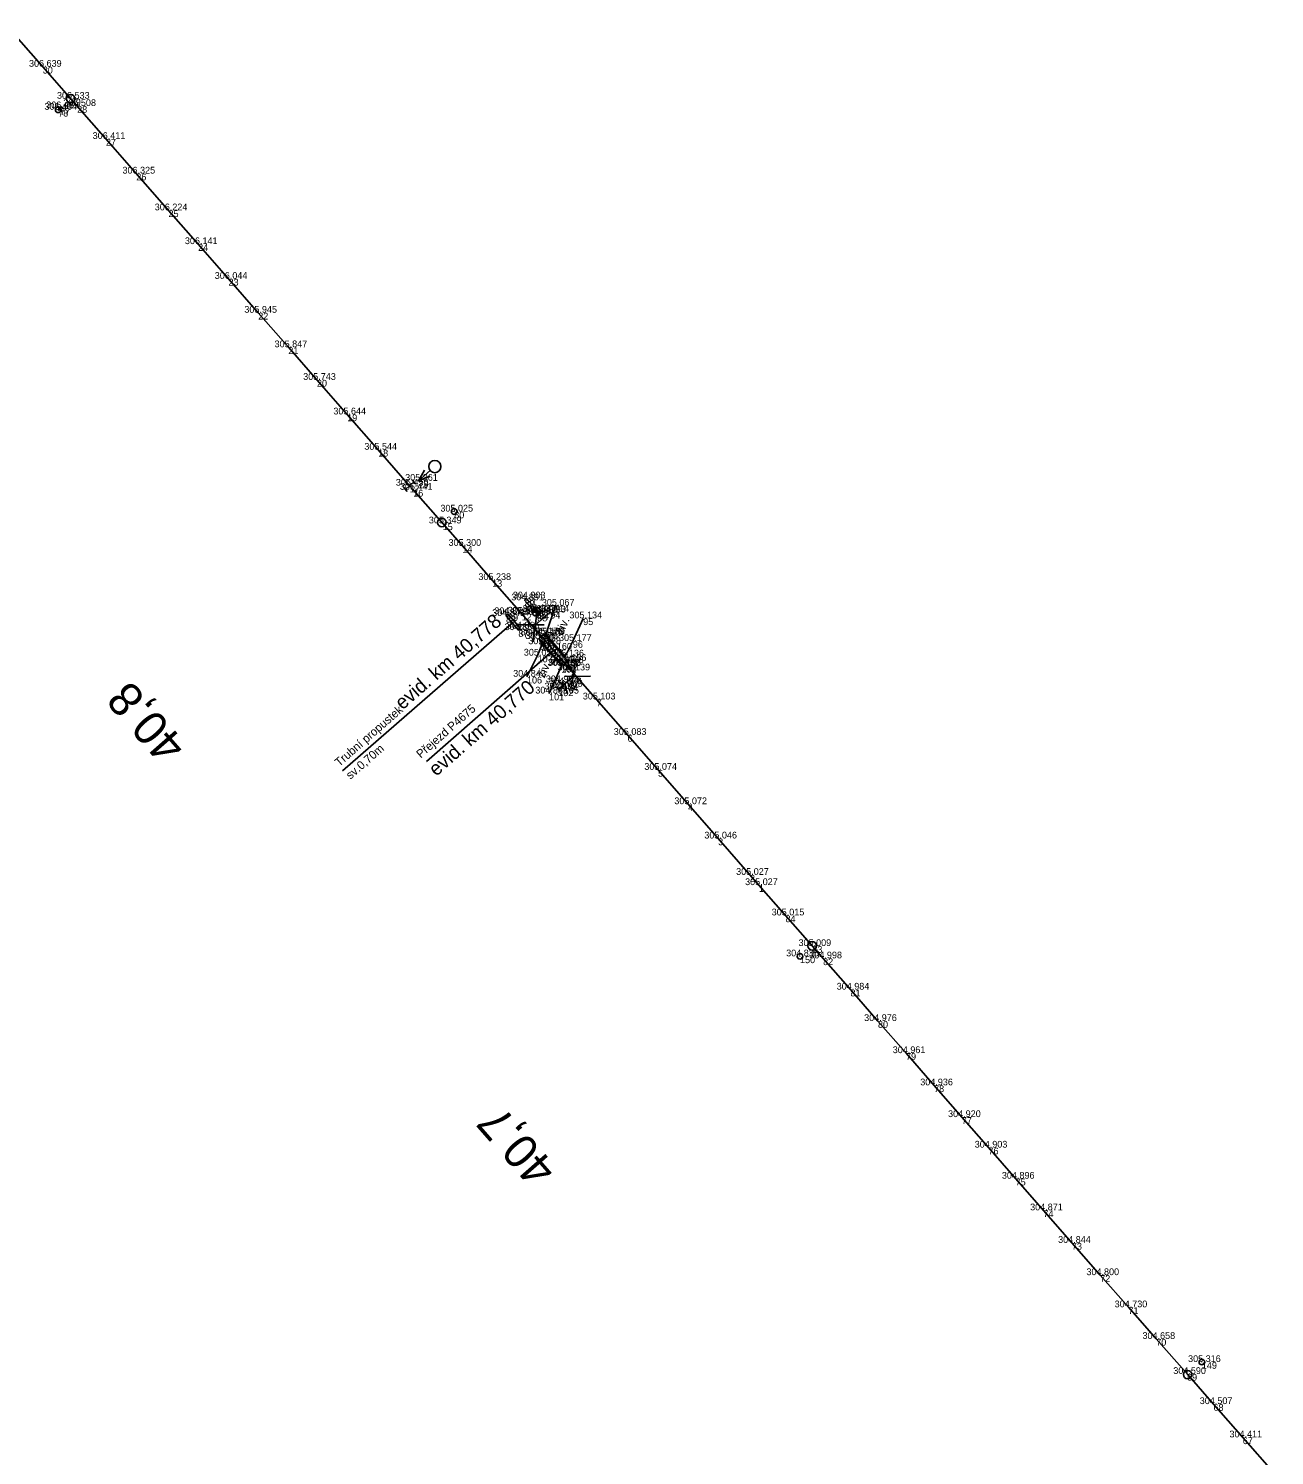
# Model space of a CAD drawing. Extents: x -684938 to -684389, y -1007777 to -1006471.
# Drawn here: x -684817.7 to -684596.3, y -1006797 to -1006543.6 of the extents above; entities that cross this region are included whole.
import ezdxf

# ---------------------------------------------------------------- set-up
doc = ezdxf.new("R2010")
doc.units = 0
for name, color, linetype in [('Vrstva 1', 7, 'Continuous'), ('Vrstva 12', 7, 'Continuous'), ('Vrstva 19', 7, 'Continuous'), ('Vrstva 3', 7, 'Continuous'), ('Vrstva 4', 7, 'Continuous'), ('Vrstva 51', 7, 'Continuous'), ('Vrstva 60', 7, 'Continuous'), ('Vrstva 61', 7, 'Continuous'), ('Vrstva 63', 7, 'Continuous'), ('Vrstva 7', 7, 'Continuous')]:
    doc.layers.add(name, color=color, linetype=linetype)

msp = doc.modelspace()

# ---------------------------------------------------------------- linework, layer by layer
at = {"layer": 'Vrstva 1'}
msp.add_lwpolyline([(-684596.33, -1006800.2), (-684601.97, -1006793.78), (-684607.16, -1006787.87), (-684611.86, -1006782.52), (-684617.33, -1006776.3), (-684622.28, -1006770.68), (-684627.29, -1006764.97), (-684632.32, -1006759.24), (-684637.38, -1006753.46), (-684642.31, -1006747.84), (-684647.14, -1006742.32), (-684651.87, -1006736.9), (-684656.8, -1006731.26), (-684661.79, -1006725.54), (-684666.77, -1006719.84), (-684671.66, -1006714.26), (-684676.52, -1006708.71), (-684678.43, -1006706.52), (-684683.2, -1006701.08), (-684687.93, -1006695.7), (-684689.52, -1006693.88), (-684695.17, -1006687.42), (-684700.5, -1006681.33), (-684705.83, -1006675.23), (-684711.26, -1006669.03), (-684716.76, -1006662.73), (-684721.27, -1006657.57), (-684722.42, -1006656.26), (-684724.49, -1006653.89), (-684726.54, -1006651.55), (-684730.09, -1006647.48), (-684735.31, -1006641.52), (-684740.61, -1006635.45), (-684744.1, -1006631.46), (-684749.34, -1006625.49), (-684749.98, -1006624.76), (-684755.57, -1006618.38), (-684761.07, -1006612.11), (-684766.44, -1006605.97), (-684771.52, -1006600.18), (-684776.88, -1006594.05), (-684782.15, -1006588.03), (-684787.55, -1006581.86), (-684792.81, -1006575.86), (-684798.53, -1006569.33), (-684803.93, -1006563.18), (-684809.04, -1006557.34), (-684810.18, -1006556.04), (-684815.15, -1006550.36), (-684821.1, -1006543.57)], dxfattribs=at)
at = {"layer": 'Vrstva 12'}
msp.add_lwpolyline([(-684723.34, -1006659.67), (-684722.75, -1006660.05), (-684722.58, -1006660.48)], dxfattribs=at)
at = {"layer": 'Vrstva 19'}
msp.add_line((-684761.93, -1006675.41), (-684731.76, -1006649.16), dxfattribs=at)
for points in [[(-684727.31, -1006647.66), (-684729.55, -1006645.12), (-684729.19, -1006644.79), (-684726.95, -1006647.34), (-684727.31, -1006647.66)], [(-684730.26, -1006650.13), (-684732.49, -1006647.58), (-684732.85, -1006647.9), (-684730.66, -1006650.41), (-684730.26, -1006650.13)]]:
    msp.add_lwpolyline(points, dxfattribs=at)
at = {"layer": 'Vrstva 3'}
for p, q in [((-684750.73, -1006625.42), (-684749.22, -1006624.1)), ((-684748.89, -1006624.48), (-684749.55, -1006623.72)), ((-684748.41, -1006623.9), (-684746.33, -1006622.08)), ((-684750.4, -1006625.79), (-684751.06, -1006625.04))]:
    msp.add_line(p, q, dxfattribs=at)
msp.add_lwpolyline([(-684747.31, -1006622.02), (-684748.41, -1006623.9), (-684746.4, -1006623.06)], dxfattribs=at)
msp.add_circle((-684745.51, -1006621.37), 1.08, dxfattribs=at)
at = {"layer": 'Vrstva 4'}
for p, q in [((-684724.98, -1006647.16), (-684727.63, -1006649.47)), ((-684724.66, -1006647.53), (-684725.31, -1006646.78)), ((-684726.1, -1006649.46), (-684730.71, -1006649.5)), ((-684728.08, -1006652.51), (-684727.41, -1006647.95)), ((-684747, -1006673.72), (-684724.43, -1006653.95)), ((-684720.48, -1006655.59), (-684721.14, -1006660.15)), ((-684723.57, -1006660.94), (-684720.92, -1006658.63)), ((-684722.46, -1006658.64), (-684717.85, -1006658.6)), ((-684723.9, -1006660.57), (-684723.24, -1006661.32))]:
    msp.add_line(p, q, dxfattribs=at)
msp.add_lwpolyline([(-684722.88, -1006656.69), (-684727, -1006651.97), (-684726.06, -1006651.16), (-684721.93, -1006655.87), (-684722.88, -1006656.69)], dxfattribs=at)
at = {"layer": 'Vrstva 51'}
for points in [[(-684724.04, -1006646.08), (-684725.76, -1006651.2), (-684722.34, -1006655.1), (-684720.98, -1006652.35), (-684719.14, -1006648.32)], [(-684729.13, -1006658.69), (-684727.24, -1006654.94), (-684726.45, -1006652.91), (-684723.02, -1006656.76), (-684725.2, -1006661.67)]]:
    msp.add_lwpolyline(points, dxfattribs=at)
at = {"layer": 'Vrstva 60'}
for p, q in [((-684815.15, -1006550.36), (-684815.15, -1006550.36)), ((-684810.18, -1006556.04), (-684810.18, -1006556.04)), ((-684812.41, -1006558), (-684812.41, -1006558)), ((-684812.08, -1006557.73), (-684812.08, -1006557.73)), ((-684809.04, -1006557.34), (-684809.04, -1006557.34)), ((-684803.93, -1006563.18), (-684803.93, -1006563.18)), ((-684798.53, -1006569.33), (-684798.53, -1006569.33)), ((-684792.81, -1006575.86), (-684792.81, -1006575.86)), ((-684787.55, -1006581.86), (-684787.55, -1006581.86)), ((-684782.15, -1006588.03), (-684782.15, -1006588.03)), ((-684776.88, -1006594.05), (-684776.88, -1006594.05)), ((-684771.52, -1006600.18), (-684771.52, -1006600.18)), ((-684766.44, -1006605.97), (-684766.44, -1006605.97)), ((-684761.07, -1006612.11), (-684761.07, -1006612.11)), ((-684755.57, -1006618.38), (-684755.57, -1006618.38)), ((-684748.41, -1006623.9), (-684748.41, -1006623.9)), ((-684749.98, -1006624.76), (-684749.98, -1006624.76)), ((-684749.34, -1006625.49), (-684749.34, -1006625.49)), ((-684742.05, -1006629.36), (-684742.05, -1006629.36)), ((-684744.1, -1006631.46), (-684744.1, -1006631.46)), ((-684740.61, -1006635.45), (-684740.61, -1006635.45)), ((-684735.31, -1006641.52), (-684735.31, -1006641.52)), ((-684729.19, -1006644.79), (-684729.19, -1006644.79)), ((-684729.55, -1006645.12), (-684729.55, -1006645.12)), ((-684727.46, -1006647.17), (-684727.46, -1006647.17)), ((-684726.95, -1006647.34), (-684726.95, -1006647.34)), ((-684724.98, -1006647.16), (-684724.98, -1006647.16)), ((-684724.04, -1006646.08), (-684724.04, -1006646.08)), ((-684732.85, -1006647.9), (-684732.85, -1006647.9)), ((-684732.49, -1006647.58), (-684732.49, -1006647.58)), ((-684730.09, -1006647.48), (-684730.09, -1006647.48)), ((-684727.31, -1006647.66), (-684727.31, -1006647.66)), ((-684719.14, -1006648.32), (-684719.14, -1006648.32)), ((-684730.66, -1006650.41), (-684730.66, -1006650.41)), ((-684730.26, -1006650.13), (-684730.26, -1006650.13)), ((-684727, -1006651.97), (-684727, -1006651.97)), ((-684726.54, -1006651.55), (-684726.54, -1006651.55)), ((-684726.06, -1006651.16), (-684726.06, -1006651.16)), ((-684725.76, -1006651.2), (-684725.76, -1006651.2)), ((-684720.98, -1006652.35), (-684720.98, -1006652.35)), ((-684727.24, -1006654.94), (-684727.24, -1006654.94)), ((-684726.45, -1006652.91), (-684726.45, -1006652.91)), ((-684724.49, -1006653.89), (-684724.49, -1006653.89)), ((-684723.02, -1006656.76), (-684723.02, -1006656.76)), ((-684722.88, -1006656.69), (-684722.88, -1006656.69)), ((-684722.42, -1006656.26), (-684722.42, -1006656.26)), ((-684722.34, -1006655.1), (-684722.34, -1006655.1)), ((-684721.93, -1006655.87), (-684721.93, -1006655.87)), ((-684729.13, -1006658.69), (-684729.13, -1006658.69)), ((-684723.34, -1006659.67), (-684723.34, -1006659.67)), ((-684721.27, -1006657.57), (-684721.27, -1006657.57)), ((-684725.2, -1006661.67), (-684725.2, -1006661.67)), ((-684723.57, -1006660.94), (-684723.57, -1006660.94)), ((-684722.75, -1006660.05), (-684722.75, -1006660.05)), ((-684722.58, -1006660.48), (-684722.58, -1006660.48)), ((-684716.76, -1006662.73), (-684716.76, -1006662.73)), ((-684711.26, -1006669.03), (-684711.26, -1006669.03)), ((-684705.83, -1006675.23), (-684705.83, -1006675.23)), ((-684700.5, -1006681.33), (-684700.5, -1006681.33)), ((-684695.17, -1006687.42), (-684695.17, -1006687.42)), ((-684689.52, -1006693.88), (-684689.52, -1006693.88)), ((-684687.93, -1006695.7), (-684687.93, -1006695.7)), ((-684683.2, -1006701.08), (-684683.2, -1006701.08)), ((-684678.43, -1006706.52), (-684678.43, -1006706.52)), ((-684680.62, -1006708.35), (-684680.62, -1006708.35)), ((-684676.52, -1006708.71), (-684676.52, -1006708.71)), ((-684671.66, -1006714.26), (-684671.66, -1006714.26)), ((-684666.77, -1006719.84), (-684666.77, -1006719.84)), ((-684661.79, -1006725.54), (-684661.79, -1006725.54)), ((-684656.8, -1006731.26), (-684656.8, -1006731.26)), ((-684651.87, -1006736.9), (-684651.87, -1006736.9)), ((-684647.14, -1006742.32), (-684647.14, -1006742.32)), ((-684642.31, -1006747.84), (-684642.31, -1006747.84)), ((-684637.38, -1006753.46), (-684637.38, -1006753.46)), ((-684632.32, -1006759.24), (-684632.32, -1006759.24)), ((-684627.29, -1006764.97), (-684627.29, -1006764.97)), ((-684622.28, -1006770.68), (-684622.28, -1006770.68)), ((-684617.33, -1006776.3), (-684617.33, -1006776.3)), ((-684609.23, -1006780.4), (-684609.23, -1006780.4)), ((-684611.86, -1006782.52), (-684611.86, -1006782.52)), ((-684607.16, -1006787.87), (-684607.16, -1006787.87)), ((-684601.97, -1006793.78), (-684601.97, -1006793.78))]:
    msp.add_line(p, q, dxfattribs=at)
at = {"layer": 'Vrstva 63'}
for p, q in [((-684727.46, -1006647.17), (-684728.22, -1006647.12)), ((-684727.44, -1006646.96), (-684728.18, -1006646.91)), ((-684727.42, -1006646.66), (-684727.99, -1006646.62)), ((-684727.51, -1006647.93), (-684727.46, -1006647.17)), ((-684727.41, -1006646.4), (-684727.46, -1006647.17)), ((-684727.46, -1006647.17), (-684726.69, -1006647.22)), ((-684726.91, -1006647.7), (-684727.49, -1006647.66)), ((-684726.73, -1006647.41), (-684727.47, -1006647.36))]:
    msp.add_line(p, q, dxfattribs=at)
msp.add_circle((-684727.46, -1006647.17), 0.764, dxfattribs=at)
for start, end in [(86.1893, 176.0828), (265.7385, 356.0566)]:
    msp.add_arc((-684727.46, -1006647.17), 0.765, start, end, dxfattribs=at)
at = {"layer": 'Vrstva 7'}
for p, q in [((-684812.46, -1006558.05), (-684811.71, -1006557.4)), ((-684812.38, -1006558.03), (-684812.44, -1006557.96)), ((-684811.76, -1006558.1), (-684812.41, -1006557.35)), ((-684742.02, -1006629.4), (-684742.09, -1006629.32)), ((-684680.59, -1006708.39), (-684680.65, -1006708.32)), ((-684609.2, -1006780.44), (-684609.26, -1006780.36))]:
    msp.add_line(p, q, dxfattribs=at)
for centre, radius in [((-684810.18, -1006556.04), 0.75), ((-684812.41, -1006558), 0.5), ((-684742.05, -1006629.36), 0.5), ((-684744.26, -1006631.29), 0.75), ((-684680.62, -1006708.35), 0.5), ((-684678.47, -1006706.48), 0.75), ((-684609.23, -1006780.4), 0.5), ((-684611.76, -1006782.63), 0.75)]:
    msp.add_circle(centre, radius, dxfattribs=at)

# ---------------------------------------------------------------- texts
at = {"layer": 'Vrstva 19'}
for s, height, p in [('evid. km 40,778', 2.5, (-684751.24, -1006664.68)), ('Trubní propustek', 1.5, (-684762.47, -1006674.73)), ('sv.0,70m', 1.5, (-684760.5, -1006677))]:
    msp.add_text(s, height=height, rotation=41.0255, dxfattribs=at).set_placement(p)
at = {"layer": 'Vrstva 4'}
for s, height, p in [('evid. km 40,770', 2.5, (-684745.25, -1006676.48)), ('Přejezd P4675', 1.5, (-684747.99, -1006673.25))]:
    msp.add_text(s, height=height, rotation=41.2098, dxfattribs=at).set_placement(p)
at = {"layer": 'Vrstva 51'}
for rotation, p in [(65.4587, (-684722.76, -1006651.28)), (66.0809, (-684726.04, -1006659.03))]:
    msp.add_text('živ.', height=1.5, rotation=rotation, dxfattribs=at).set_placement(p)
at = {"layer": 'Vrstva 60'}
for s, p in [('30', (-684815.15, -1006551.56)), ('29', (-684810.18, -1006557.24)), ('78', (-684812.41, -1006559.2)), ('77', (-684812.08, -1006558.93)), ('28', (-684809.04, -1006558.54)), ('27', (-684803.93, -1006564.38)), ('26', (-684798.53, -1006570.53)), ('25', (-684792.81, -1006577.06)), ('24', (-684787.55, -1006583.06)), ('23', (-684782.15, -1006589.23)), ('22', (-684776.88, -1006595.25)), ('21', (-684771.52, -1006601.38)), ('20', (-684766.44, -1006607.17)), ('19', (-684761.07, -1006613.31)), ('18', (-684755.57, -1006619.58)), ('79', (-684748.41, -1006625.1)), ('17', (-684749.98, -1006625.96)), ('16', (-684749.34, -1006626.69)), ('80', (-684742.05, -1006630.56)), ('15', (-684744.1, -1006632.66)), ('14', (-684740.61, -1006636.65)), ('13', (-684735.31, -1006642.71)), ('81', (-684729.19, -1006645.99)), ('82', (-684729.55, -1006646.32)), ('85', (-684727.46, -1006648.37)), ('84', (-684726.95, -1006648.54)), ('94', (-684724.98, -1006648.36)), ('93', (-684724.04, -1006647.28)), ('88', (-684732.85, -1006649.1)), ('89', (-684732.49, -1006648.78)), ('12', (-684730.09, -1006648.68)), ('83', (-684727.31, -1006648.85)), ('95', (-684719.14, -1006649.52)), ('87', (-684730.66, -1006651.61)), ('86', (-684730.26, -1006651.33)), ('90', (-684727, -1006653.17)), ('11', (-684726.54, -1006652.75)), ('91', (-684726.06, -1006652.36)), ('92', (-684725.76, -1006652.4)), ('96', (-684720.98, -1006653.55)), ('107', (-684727.24, -1006656.14)), ('108', (-684726.45, -1006654.11)), ('10', (-684724.49, -1006655.09)), ('100', (-684723.02, -1006657.96)), ('99', (-684722.88, -1006657.89)), ('9', (-684722.42, -1006657.46)), ('97', (-684722.34, -1006656.3)), ('98', (-684721.93, -1006657.07)), ('106', (-684729.13, -1006659.89)), ('103', (-684723.34, -1006660.87)), ('8', (-684721.27, -1006658.77)), ('101', (-684725.2, -1006662.87)), ('102', (-684723.57, -1006662.14)), ('104', (-684722.75, -1006661.25)), ('105', (-684722.58, -1006661.68)), ('7', (-684716.76, -1006663.93)), ('6', (-684711.26, -1006670.23)), ('5', (-684705.83, -1006676.44)), ('4', (-684700.5, -1006682.53)), ('3', (-684695.17, -1006688.62)), ('2', (-684689.52, -1006695.08)), ('1', (-684687.93, -1006696.9)), ('84', (-684683.2, -1006702.28)), ('83', (-684678.43, -1006707.72)), ('150', (-684680.62, -1006709.56)), ('82', (-684676.52, -1006709.91)), ('81', (-684671.66, -1006715.46)), ('80', (-684666.77, -1006721.04)), ('79', (-684661.79, -1006726.74)), ('78', (-684656.8, -1006732.46)), ('77', (-684651.87, -1006738.1)), ('76', (-684647.14, -1006743.52)), ('75', (-684642.31, -1006749.04)), ('74', (-684637.38, -1006754.66)), ('73', (-684632.32, -1006760.44)), ('72', (-684627.29, -1006766.17)), ('71', (-684622.28, -1006771.88)), ('70', (-684617.33, -1006777.5)), ('149', (-684609.23, -1006781.6)), ('69', (-684611.86, -1006783.72)), ('68', (-684607.16, -1006789.07)), ('67', (-684601.97, -1006794.98))]:
    msp.add_text(s, height=1.2, dxfattribs=at).set_placement(p)
at = {"layer": 'Vrstva 61'}
for s, p in [('306.639', (-684817.6, -1006550.36)), ('306.533', (-684812.63, -1006556.04)), ('306.464', (-684814.86, -1006558)), ('306.489', (-684814.54, -1006557.73)), ('306.508', (-684811.5, -1006557.34)), ('306.411', (-684806.29, -1006563.18)), ('306.325', (-684800.99, -1006569.33)), ('306.224', (-684795.26, -1006575.86)), ('306.141', (-684789.9, -1006581.86)), ('306.044', (-684784.6, -1006588.03)), ('305.945', (-684779.34, -1006594.05)), ('305.847', (-684773.97, -1006600.18)), ('305.743', (-684768.89, -1006605.97)), ('305.644', (-684763.52, -1006612.11)), ('305.544', (-684758.02, -1006618.38)), ('305.450', (-684752.43, -1006624.76)), ('305.441', (-684751.7, -1006625.49)), ('305.361', (-684750.77, -1006623.9)), ('305.025', (-684744.51, -1006629.36)), ('305.349', (-684746.56, -1006631.46)), ('305.300', (-684743.07, -1006635.45)), ('305.238', (-684737.76, -1006641.52)), ('304.891', (-684731.91, -1006645.12)), ('304.903', (-684731.64, -1006644.79)), ('304.843', (-684735.3, -1006647.9)), ('304.879', (-684734.94, -1006647.58)), ('305.198', (-684732.55, -1006647.48)), ('304.937', (-684729.91, -1006647.17)), ('304.902', (-684729.76, -1006647.66)), ('304.881', (-684729.3, -1006647.34)), ('304.914', (-684727.44, -1006647.16)), ('305.067', (-684726.49, -1006646.08)), ('305.134', (-684721.59, -1006648.32)), ('304.856', (-684733.12, -1006650.41)), ('304.866', (-684732.71, -1006650.13)), ('305.176', (-684729.45, -1006651.97)), ('305.170', (-684728.99, -1006651.55)), ('305.128', (-684728.9, -1006652.91)), ('305.178', (-684728.51, -1006651.16)), ('305.163', (-684728.22, -1006651.2)), ('305.177', (-684723.44, -1006652.35)), ('305.054', (-684729.69, -1006654.94)), ('305.160', (-684726.94, -1006653.89)), ('305.136', (-684724.8, -1006655.1)), ('305.156', (-684724.38, -1006655.87)), ('304.843', (-684731.58, -1006658.69)), ('305.132', (-684725.47, -1006656.76)), ('305.153', (-684725.33, -1006656.69)), ('305.148', (-684724.87, -1006656.26)), ('305.139', (-684723.72, -1006657.57)), ('304.697', (-684726.02, -1006660.94)), ('304.963', (-684725.79, -1006659.67)), ('304.878', (-684725.21, -1006660.05)), ('304.765', (-684725.04, -1006660.48)), ('304.885', (-684727.65, -1006661.67)), ('305.103', (-684719.21, -1006662.73)), ('305.083', (-684713.71, -1006669.03)), ('305.074', (-684708.28, -1006675.23)), ('305.072', (-684702.95, -1006681.33)), ('305.046', (-684697.62, -1006687.42)), ('305.027', (-684691.97, -1006693.88)), ('305.027', (-684690.38, -1006695.7)), ('305.015', (-684685.66, -1006701.08)), ('305.009', (-684680.89, -1006706.52)), ('304.835', (-684683.08, -1006708.35)), ('304.998', (-684678.97, -1006708.71)), ('304.984', (-684674.11, -1006714.26)), ('304.976', (-684669.23, -1006719.84)), ('304.961', (-684664.15, -1006725.54)), ('304.936', (-684659.26, -1006731.26)), ('304.920', (-684654.32, -1006736.9)), ('304.903', (-684649.59, -1006742.32)), ('304.896', (-684644.76, -1006747.84)), ('304.871', (-684639.74, -1006753.46)), ('304.844', (-684634.77, -1006759.24)), ('304.800', (-684629.74, -1006764.97)), ('304.730', (-684624.73, -1006770.68)), ('304.658', (-684619.78, -1006776.3)), ('304.590', (-684614.31, -1006782.52)), ('305.316', (-684611.68, -1006780.4)), ('304.507', (-684609.61, -1006787.87)), ('304.411', (-684604.33, -1006793.78))]:
    msp.add_text(s, height=1.2, dxfattribs=at).set_placement(p)
at = {"layer": 'Vrstva 7'}
for s, rotation, p in [('40,8', 131.2287, (-684789.38, -1006670.83)), ('40,7', 131.2396, (-684723.59, -1006746.03))]:
    msp.add_text(s, height=6, rotation=rotation, dxfattribs=at).set_placement(p)

doc.saveas('drawing.dxf')
